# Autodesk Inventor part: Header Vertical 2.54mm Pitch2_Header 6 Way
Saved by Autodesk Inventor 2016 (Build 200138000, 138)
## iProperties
Created: 2012-01
Part Number: Header Vertical 2.54mm Pitch2_Header 6 Way
Document SubType Name: Modeling
Designer: Trevor
Density: 1 g/cm^3
Material: Generic
Appearance: Default
Author: Trevor
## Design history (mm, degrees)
feature "Base1"
feature "Base2"
feature "Base3"
feature "Base4"
feature "Base5"
feature "Base6"
node "Chafl�n2"
node "Matriz[1]"
node "Matriz[2]"
node "Matriz[3]"
node "Matriz[4]"
node "Matriz[5]"
